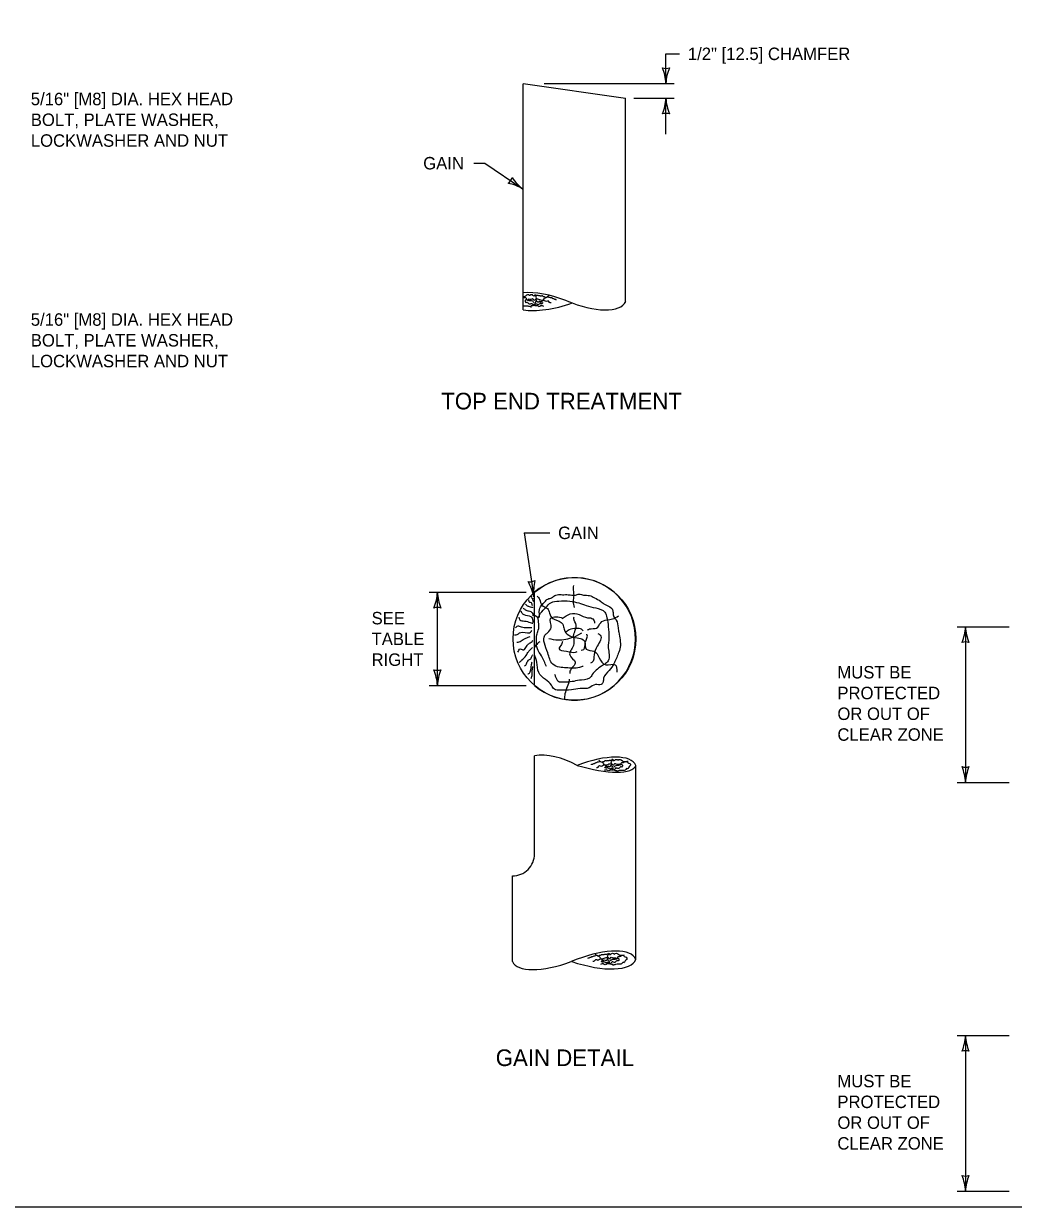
# Model space of a CAD drawing. Extents: x 49991.4 to 50021, y 49987.6 to 50011.4.
# Drawn here: x 50004.08 to 50008.84, y 49987.8 to 49993.5 of the extents above; entities that cross this region are included whole.
import ezdxf

# ---------------------------------------------------------------- set-up
doc = ezdxf.new("R2010")
doc.units = 0
for name, color, linetype in [('Level 1', 7, 'Continuous'), ('Level 2', 7, 'Continuous'), ('Level 3', 7, 'Continuous')]:
    doc.layers.add(name, color=color, linetype=linetype)

msp = doc.modelspace()

# ---------------------------------------------------------------- linework, layer by layer
at = {"layer": 'Level 1'}
for p, q in [((50006.4832, 49992.1206), (50006.4832, 49993.2096)), ((50006.4833, 49993.2102), (50006.9756, 49993.14)), ((50006.9757, 49992.1613), (50006.9757, 49993.14)), ((50006.5375, 49990.3115), (50006.5375, 49990.7608)), ((50006.7246, 49990.5433), (50006.7654, 49990.566)), ((50006.5375, 49989.5007), (50006.5375, 49989.9737)), ((50007.0253, 49988.9933), (50007.0253, 49989.9272)), ((50006.4312, 49988.9827), (50006.4312, 49989.3948)), ((50006.7429, 49988.9933), (50006.7137, 49988.9827))]:
    msp.add_line(p, q, dxfattribs=at)
msp.add_lwpolyline([(49999.3835, 49998.9992), (50016.7501, 49998.9992), (50016.7501, 49987.7988), (49999.3835, 49987.7988)], close=True, dxfattribs=at)
msp.add_circle((50006.7296, 49990.5361), 0.2956, dxfattribs=at)
for centre, radius, start, end in [((50006.7288, 49990.5361), 0.2951, 229.3594, 130.4189), ((50006.4316, 49989.5007), 0.1059, 269.7855, 359.9985)]:
    msp.add_arc(centre, radius, start, end, dxfattribs=at)
for centre, major_axis, ratio, start_param, end_param in [((50006.6565, 49992.069), (-0.2457, 0.0951), 0.387082, 4.71239, 5.63336), ((50006.6874, 49992.2618), (-0.2766, -0.0977), 0.384401, 0.614947, 1.552667), ((50006.7369, 49992.2649), (0.2396, -0.1036), 0.420526, 4.712389, 6.280066), ((50006.7369, 49992.2649), (0.2396, -0.1036), 0.420526, 6.282738, 6.283185), ((50006.6796, 49989.8095), (-0.2192, 0.1177), 0.537084, 4.712389, 5.665612), ((50006.7797, 49989.8321), (0.2457, 0.0951), 0.387082, 0, 1.570796), ((50006.7668, 49990.006), (0.2585, -0.0788), 0.304673, 4.712389, 6.283185), ((50006.7797, 49988.8982), (0.2457, 0.0951), 0.387082, 0, 1.570569), ((50006.6768, 49989.0778), (-0.2457, -0.0951), 0.387082, 0, 1.570796), ((50006.7488, 49989.091), (0.2766, -0.0977), 0.384401, 4.733049, 6.283185)]:
    msp.add_ellipse(centre, major_axis=major_axis, ratio=ratio, start_param=start_param, end_param=end_param, dxfattribs=at)
for points in [[(50006.641, 49992.1677), (50006.641, 49992.1706), (50006.6352, 49992.1706), (50006.6309, 49992.1735), (50006.6266, 49992.1735), (50006.6223, 49992.1778), (50006.6179, 49992.1778), (50006.6121, 49992.1807), (50006.6078, 49992.1807), (50006.5992, 49992.1836), (50006.5906, 49992.1793), (50006.5862, 49992.1836), (50006.5805, 49992.1836), (50006.5761, 49992.1879), (50006.5689, 49992.1865), (50006.5646, 49992.1879), (50006.5603, 49992.1879), (50006.5545, 49992.1893), (50006.5502, 49992.1893), (50006.5444, 49992.1908), (50006.5372, 49992.1908), (50006.5372, 49992.1879), (50006.5329, 49992.1879), (50006.5271, 49992.1922), (50006.5185, 49992.1922), (50006.5141, 49992.1893), (50006.5098, 49992.1922), (50006.4983, 49992.1908), (50006.4882, 49992.1836), (50006.4832, 49992.1836)], [(50006.5343, 49992.1562), (50006.5285, 49992.162), (50006.517, 49992.1648), (50006.504, 49992.1663), (50006.4954, 49992.1778), (50006.4896, 49992.1778), (50006.4853, 49992.1793), (50006.4832, 49992.1801)], [(50006.6179, 49992.1548), (50006.6093, 49992.1562), (50006.6035, 49992.1634), (50006.5948, 49992.1606), (50006.5862, 49992.1648), (50006.5733, 49992.1663), (50006.5631, 49992.1692), (50006.543, 49992.1706), (50006.5343, 49992.1663), (50006.53, 49992.1735), (50006.5243, 49992.1721), (50006.5156, 49992.1706), (50006.507, 49992.1706), (50006.5055, 49992.1663), (50006.4998, 49992.1692), (50006.4954, 49992.1692), (50006.4925, 49992.1606), (50006.4954, 49992.1562), (50006.4998, 49992.1576), (50006.5055, 49992.1548), (50006.5113, 49992.149), (50006.5243, 49992.1519), (50006.5329, 49992.1433), (50006.5444, 49992.1418), (50006.5502, 49992.1418), (50006.5588, 49992.1375), (50006.5675, 49992.1418), (50006.5805, 49992.1389)], [(50006.5488, 49992.162), (50006.5444, 49992.1721), (50006.5473, 49992.1793), (50006.543, 49992.1879), (50006.5401, 49992.1951)], [(50006.5631, 49992.1562), (50006.5805, 49992.1692), (50006.5862, 49992.1764), (50006.6006, 49992.1836), (50006.6064, 49992.1893)], [(50006.4832, 49992.1407), (50006.4839, 49992.1403), (50006.4925, 49992.1403), (50006.5084, 49992.1389), (50006.5228, 49992.1346)], [(50006.5386, 49992.1461), (50006.5285, 49992.1403), (50006.5199, 49992.1403)], [(50006.5747, 49992.1576), (50006.5689, 49992.1591), (50006.5588, 49992.1606), (50006.556, 49992.1576), (50006.5502, 49992.1606), (50006.543, 49992.1606), (50006.5401, 49992.1461), (50006.5458, 49992.1504), (50006.5502, 49992.1476), (50006.5574, 49992.1476), (50006.5646, 49992.1519), (50006.5733, 49992.1504), (50006.5761, 49992.1533), (50006.5776, 49992.1562)], [(50006.5713, 49990.6976), (50006.5866, 49990.7145), (50006.6015, 49990.7282), (50006.6198, 49990.734), (50006.6348, 49990.7448), (50006.6469, 49990.7491), (50006.6724, 49990.7491), (50006.6996, 49990.7491), (50006.7341, 49990.7474), (50006.7525, 49990.7521), (50006.7736, 49990.7474), (50006.8022, 49990.7448), (50006.8264, 49990.734), (50006.855, 49990.7174), (50006.8715, 49990.7053), (50006.908, 49990.6843), (50006.9152, 49990.6679), (50006.917, 49990.6479), (50006.9307, 49990.6268), (50006.9396, 49990.5893), (50006.9426, 49990.568), (50006.95, 49990.4958), (50006.9409, 49990.4655), (50006.9186, 49990.4157), (50006.8972, 49990.3838), (50006.8702, 49990.3476), (50006.8672, 49990.3283), (50006.8581, 49990.3161), (50006.8308, 49990.3161), (50006.8006, 49990.301), (50006.757, 49990.2965), (50006.7147, 49990.2905), (50006.6606, 49990.289), (50006.6334, 49990.2933), (50006.6198, 49990.3129), (50006.5895, 49990.3403), (50006.5577, 49990.3749), (50006.5487, 49990.4233), (50006.5375, 49990.459)], [(50006.7297, 49990.6875), (50006.7246, 49990.7167), (50006.7278, 49990.7451), (50006.7246, 49990.7815), (50006.7262, 49990.7934)], [(50006.4943, 49990.7031), (50006.5061, 49990.6943), (50006.5076, 49990.6943), (50006.5165, 49990.6899), (50006.5268, 49990.6884), (50006.5283, 49990.6854)], [(50006.5091, 49990.7238), (50006.5135, 49990.7135), (50006.5165, 49990.7135), (50006.5238, 49990.7046), (50006.5268, 49990.6987), (50006.5283, 49990.6987)], [(50006.5224, 49990.7415), (50006.5224, 49990.7341), (50006.5297, 49990.7312), (50006.5283, 49990.7267), (50006.5327, 49990.7164)], [(50006.5375, 49990.6508), (50006.5593, 49990.6405), (50006.5608, 49990.6782), (50006.573, 49990.6994)], [(50006.5498, 49990.7423), (50006.5619, 49990.727), (50006.5724, 49990.6985), (50006.5996, 49990.6819), (50006.6103, 49990.6593), (50006.625, 49990.6337), (50006.6313, 49990.6307), (50006.6735, 49990.6067), (50006.6795, 49990.5823), (50006.7021, 49990.5536), (50006.7246, 49990.5433)], [(50006.5529, 49990.6351), (50006.5664, 49990.6593), (50006.5919, 49990.6877), (50006.6162, 49990.7105), (50006.6541, 49990.7181), (50006.7081, 49990.7181), (50006.7503, 49990.7091), (50006.7867, 49990.6968), (50006.832, 49990.685), (50006.8758, 49990.6652), (50006.8862, 49990.638), (50006.8925, 49990.5944), (50006.8954, 49990.5415), (50006.8925, 49990.4933), (50006.8925, 49990.4312), (50006.874, 49990.4132), (50006.8559, 49990.4028), (50006.8349, 49990.3863), (50006.8154, 49990.365), (50006.8108, 49990.3545), (50006.764, 49990.338), (50006.7262, 49990.3317), (50006.6932, 49990.3273), (50006.6722, 49990.3273), (50006.6541, 49990.329), (50006.6404, 49990.3517), (50006.6354, 49990.3653)], [(50006.4619, 49990.6412), (50006.4663, 49990.6279), (50006.4899, 49990.622), (50006.5165, 49990.6146), (50006.5253, 49990.6117), (50006.5297, 49990.6117)], [(50006.4722, 49990.6707), (50006.4752, 49990.6633), (50006.4855, 49990.653), (50006.5194, 49990.6441), (50006.5224, 49990.6412), (50006.5297, 49990.6146)], [(50006.4825, 49990.6854), (50006.4929, 49990.6766), (50006.5091, 49990.6707), (50006.5268, 49990.6618), (50006.5297, 49990.6515), (50006.5297, 49990.6471)], [(50006.5944, 49990.403), (50006.571, 49990.454), (50006.5512, 49990.4886), (50006.5466, 49990.5266), (50006.5482, 49990.5551), (50006.5557, 49990.5779), (50006.5529, 49990.6412)], [(50006.7724, 49990.4057), (50006.7537, 49990.3981), (50006.6901, 49990.3967), (50006.657, 49990.4), (50006.625, 49990.4148), (50006.601, 49990.4693), (50006.5876, 49990.5536), (50006.5996, 49990.5657), (50006.6178, 49990.5914), (50006.6147, 49990.6351), (50006.6416, 49990.6428), (50006.6722, 49990.6365)], [(50006.6706, 49990.6337), (50006.7098, 49990.6565), (50006.7518, 49990.6531), (50006.7927, 49990.638), (50006.8139, 49990.6351), (50006.8259, 49990.6185), (50006.8264, 49990.6111)], [(50006.7246, 49990.5433), (50006.7309, 49990.5703), (50006.7384, 49990.6017), (50006.7262, 49990.6351), (50006.7275, 49990.6421)], [(50006.7918, 49990.5792), (50006.8018, 49990.5839), (50006.8366, 49990.5883), (50006.8559, 49990.6139), (50006.8848, 49990.6275), (50006.9134, 49990.632), (50006.9421, 49990.6472)], [(50006.5238, 49990.5896), (50006.4943, 49990.5896), (50006.4929, 49990.5896), (50006.4693, 49990.594), (50006.4619, 49990.5969), (50006.453, 49990.5955), (50006.4457, 49990.5896)], [(50006.7719, 49990.5749), (50006.764, 49990.5823), (50006.7384, 49990.5867), (50006.7038, 49990.5793), (50006.6888, 49990.5686)], [(50006.4412, 49990.5556), (50006.4486, 49990.5556), (50006.4707, 49990.5674), (50006.5135, 49990.566), (50006.5224, 49990.5733), (50006.5238, 49990.5763)], [(50006.453, 49990.5202), (50006.4589, 49990.5202), (50006.4781, 49990.5306), (50006.4884, 49990.5365), (50006.4958, 49990.5394), (50006.5165, 49990.5483)], [(50006.4575, 49990.4716), (50006.4693, 49990.4878), (50006.4855, 49990.4834), (50006.4988, 49990.4996), (50006.5106, 49990.5129), (50006.5165, 49990.5173), (50006.5253, 49990.5232), (50006.5312, 49990.5291)], [(50006.5622, 49990.5218), (50006.5437, 49990.5053), (50006.5375, 49990.4966)], [(50006.7246, 49990.5433), (50006.6508, 49990.5295), (50006.6058, 49990.5365)], [(50006.6714, 49990.5237), (50006.6674, 49990.5098), (50006.6553, 49990.4886), (50006.6915, 49990.4767), (50006.7354, 49990.4721), (50006.7426, 49990.4748)], [(50006.7246, 49990.5433), (50006.7246, 49990.5038), (50006.7068, 49990.4586), (50006.7336, 49990.4238), (50006.7081, 49990.3801), (50006.7071, 49990.3698)], [(50006.7246, 49990.5433), (50006.779, 49990.5219), (50006.7867, 49990.4873), (50006.8244, 49990.4767), (50006.8486, 49990.445), (50006.8802, 49990.4119), (50006.9253, 49990.4119), (50006.9331, 49990.3757)], [(50006.7624, 49990.4815), (50006.7746, 49990.4858), (50006.782, 49990.5191), (50006.7897, 49990.5581), (50006.789, 49990.559)], [(50006.8416, 49990.5623), (50006.8546, 49990.5536), (50006.8394, 49990.5009), (50006.8244, 49990.46), (50006.8139, 49990.4223), (50006.8071, 49990.4198)], [(50006.4648, 49990.4229), (50006.4752, 49990.4332), (50006.4973, 49990.4568), (50006.5076, 49990.4745), (50006.5194, 49990.4863), (50006.5238, 49990.4907), (50006.5283, 49990.4952)], [(50006.4899, 49990.4052), (50006.4988, 49990.4155), (50006.5076, 49990.4332), (50006.5194, 49990.4406), (50006.5268, 49990.4553), (50006.5297, 49990.4598)], [(50006.5047, 49990.3683), (50006.5061, 49990.3683), (50006.5209, 49990.3963), (50006.5224, 49990.4096), (50006.5253, 49990.4258)], [(50006.5209, 49990.3447), (50006.5253, 49990.3595), (50006.5268, 49990.386), (50006.5297, 49990.4037)], [(50006.7042, 49990.3428), (50006.7038, 49990.338), (50006.6946, 49990.3049), (50006.684, 49990.2715), (50006.6813, 49990.2445)], [(50006.8125, 49989.9304), (50006.8125, 49989.9334), (50006.8183, 49989.9334), (50006.8226, 49989.9362), (50006.8269, 49989.9362), (50006.8312, 49989.9406), (50006.8356, 49989.9406), (50006.8414, 49989.9434), (50006.8457, 49989.9434), (50006.8543, 49989.9463), (50006.863, 49989.942), (50006.8673, 49989.9463), (50006.873, 49989.9463), (50006.8774, 49989.9506), (50006.8846, 49989.9492), (50006.8889, 49989.9506), (50006.8933, 49989.9506), (50006.899, 49989.9521), (50006.9033, 49989.9521), (50006.9091, 49989.9535), (50006.9163, 49989.9535), (50006.9163, 49989.9506), (50006.9206, 49989.9506), (50006.9264, 49989.9549), (50006.935, 49989.9549), (50006.9394, 49989.9521), (50006.9437, 49989.9549), (50006.9552, 49989.9535), (50006.9653, 49989.9463), (50006.9768, 49989.9463), (50006.9826, 49989.9449), (50006.9869, 49989.9406), (50006.9956, 49989.9362), (50006.9999, 49989.929), (50006.9985, 49989.9261), (50006.9913, 49989.9189), (50006.9855, 49989.9103), (50006.9826, 49989.9131), (50006.9768, 49989.9074), (50006.9696, 49989.9031), (50006.961, 49989.9031), (50006.9451, 49989.9016), (50006.9308, 49989.8973)], [(50006.8904, 49989.9189), (50006.873, 49989.9319), (50006.8673, 49989.9391), (50006.8529, 49989.9463), (50006.8471, 49989.9521)], [(50006.9048, 49989.9247), (50006.9091, 49989.9348), (50006.9063, 49989.942), (50006.9105, 49989.9506), (50006.9134, 49989.9579)], [(50006.8356, 49989.9175), (50006.8442, 49989.9189), (50006.85, 49989.9261), (50006.8587, 49989.9233), (50006.8673, 49989.9276), (50006.8802, 49989.929), (50006.8904, 49989.9319), (50006.9105, 49989.9334), (50006.9192, 49989.929), (50006.9235, 49989.9362), (50006.9293, 49989.9348), (50006.9379, 49989.9334), (50006.9466, 49989.9334), (50006.948, 49989.929), (50006.9538, 49989.9319), (50006.9581, 49989.9319), (50006.961, 49989.9233), (50006.9581, 49989.9189), (50006.9538, 49989.9204), (50006.948, 49989.9175), (50006.9423, 49989.9117), (50006.9293, 49989.9146), (50006.9206, 49989.906), (50006.9091, 49989.9045), (50006.9033, 49989.9045), (50006.8947, 49989.9002), (50006.886, 49989.9045), (50006.873, 49989.9016)], [(50006.8788, 49989.9204), (50006.8846, 49989.9218), (50006.8947, 49989.9233), (50006.8975, 49989.9204), (50006.9033, 49989.9233), (50006.9105, 49989.9233), (50006.9134, 49989.9088), (50006.9077, 49989.9131), (50006.9033, 49989.9103), (50006.8961, 49989.9103), (50006.8889, 49989.9146), (50006.8802, 49989.9131), (50006.8774, 49989.9161), (50006.876, 49989.9189)], [(50006.9149, 49989.9088), (50006.925, 49989.9031), (50006.9336, 49989.9031)], [(50006.9192, 49989.9189), (50006.925, 49989.9247), (50006.9365, 49989.9276), (50006.9495, 49989.929), (50006.9581, 49989.9406), (50006.9639, 49989.9406), (50006.9682, 49989.942), (50006.9783, 49989.9463), (50006.9884, 49989.9478)], [(50006.7952, 49988.9969), (50006.7952, 49988.9998), (50006.801, 49988.9998), (50006.8052, 49989.0027), (50006.8096, 49989.0027), (50006.8139, 49989.007), (50006.8182, 49989.007), (50006.824, 49989.0099), (50006.8283, 49989.0099), (50006.837, 49989.0127), (50006.8456, 49989.0084), (50006.85, 49989.0127), (50006.8557, 49989.0127), (50006.86, 49989.0171), (50006.8673, 49989.0157), (50006.8715, 49989.0171), (50006.8759, 49989.0171), (50006.8817, 49989.0185), (50006.886, 49989.0185), (50006.8918, 49989.0199), (50006.899, 49989.0199), (50006.899, 49989.0171), (50006.9033, 49989.0171), (50006.909, 49989.0214), (50006.9177, 49989.0214), (50006.922, 49989.0185), (50006.9263, 49989.0214), (50006.9378, 49989.0199), (50006.948, 49989.0127), (50006.9595, 49989.0127), (50006.9653, 49989.0113), (50006.9696, 49989.007), (50006.9782, 49989.0027), (50006.9826, 49988.9954), (50006.9811, 49988.9926), (50006.9739, 49988.9854), (50006.9681, 49988.9767), (50006.9653, 49988.9796), (50006.9595, 49988.9739), (50006.9523, 49988.9695), (50006.9436, 49988.9695), (50006.9278, 49988.9681), (50006.9134, 49988.9637)], [(50006.8182, 49988.9839), (50006.8269, 49988.9854), (50006.8327, 49988.9926), (50006.8413, 49988.9897), (50006.85, 49988.994), (50006.8629, 49988.9954), (50006.873, 49988.9984), (50006.8932, 49988.9998), (50006.9018, 49988.9954), (50006.9062, 49989.0027), (50006.9119, 49989.0012), (50006.9206, 49988.9998), (50006.9292, 49988.9998), (50006.9307, 49988.9954), (50006.9364, 49988.9984), (50006.9408, 49988.9984), (50006.9436, 49988.9897), (50006.9408, 49988.9854), (50006.9364, 49988.9868), (50006.9307, 49988.9839), (50006.9249, 49988.9782), (50006.9119, 49988.9811), (50006.9033, 49988.9724), (50006.8918, 49988.9709), (50006.886, 49988.9709), (50006.8773, 49988.9666), (50006.8687, 49988.9709), (50006.8557, 49988.9681)], [(50006.873, 49988.9854), (50006.8557, 49988.9984), (50006.85, 49989.0056), (50006.8355, 49989.0127), (50006.8297, 49989.0185)], [(50006.8615, 49988.9868), (50006.8673, 49988.9882), (50006.8773, 49988.9897), (50006.8802, 49988.9868), (50006.886, 49988.9897), (50006.8932, 49988.9897), (50006.896, 49988.9753), (50006.8903, 49988.9796), (50006.886, 49988.9767), (50006.8788, 49988.9767), (50006.8715, 49988.9811), (50006.8629, 49988.9796), (50006.86, 49988.9825), (50006.8586, 49988.9854)], [(50006.8874, 49988.9912), (50006.8918, 49989.0012), (50006.8889, 49989.0084), (50006.8932, 49989.0171), (50006.896, 49989.0243)], [(50006.9018, 49988.9854), (50006.9076, 49988.9912), (50006.9191, 49988.994), (50006.9321, 49988.9954), (50006.9408, 49989.007), (50006.9466, 49989.007), (50006.9508, 49989.0084), (50006.9609, 49989.0127), (50006.9711, 49989.0142)], [(50006.8975, 49988.9753), (50006.9076, 49988.9695), (50006.9163, 49988.9695)]]:
    msp.add_spline(points, degree=3, dxfattribs=at)
at = {"layer": 'Level 3'}
for p, q in [((50007.1701, 49993.3536), (50007.2358, 49993.3536)), ((50007.1701, 49993.2102), (50007.1701, 49993.3536)), ((50006.5833, 49993.2102), (50007.2101, 49993.2102)), ((50007.0157, 49993.14), (50007.2101, 49993.14)), ((50007.1701, 49992.9666), (50007.1701, 49993.14)), ((50006.2444, 49992.8269), (50006.2982, 49992.8269)), ((50006.2982, 49992.8269), (50006.4832, 49992.7014)), ((50006.487, 49991.0468), (50006.6109, 49991.0468)), ((50006.487, 49991.0468), (50006.5343, 49990.7391)), ((50006.0297, 49990.7608), (50006.4975, 49990.7608)), ((50006.0697, 49990.3115), (50006.0697, 49990.7608)), ((50008.5724, 49990.5949), (50008.8227, 49990.5949)), ((50008.6124, 49990.5949), (50008.6124, 49989.8449)), ((50006.0297, 49990.3115), (50006.4975, 49990.3115)), ((50008.5724, 49989.8449), (50008.8227, 49989.8449)), ((50008.5724, 49988.6261), (50008.8227, 49988.6261)), ((50008.6124, 49988.6261), (50008.6124, 49987.8761)), ((50008.5724, 49987.8761), (50008.8227, 49987.8761))]:
    msp.add_line(p, q, dxfattribs=at)
for centre, radius, start, end in [((50007.1701, 49993.3384), 0.0548, 252.1388, 287.8612), ((50006.9374, 49993.1987), 0.233, 2.8273, 22.0772), ((50007.3922, 49993.201), 0.2223, 157.456, 177.6395), ((50006.948, 49993.1492), 0.2223, 337.456, 357.6395), ((50007.4028, 49993.1515), 0.233, 182.8273, 202.0772), ((50007.1701, 49993.0118), 0.0548, 72.1388, 107.8612), ((50006.3771, 49992.7734), 0.0548, 307.9799, 343.7022), ((50006.6155, 49992.88), 0.2223, 213.2971, 233.4806), ((50006.362, 49992.5023), 0.233, 58.6684, 77.9182), ((50006.5148, 49990.8658), 0.0548, 260.878, 296.6003), ((50006.306, 49990.6924), 0.233, 11.5665, 30.8163), ((50006.7552, 49990.7638), 0.2223, 166.1952, 186.3787), ((50005.8476, 49990.77), 0.2223, 337.456, 357.6395), ((50006.3024, 49990.7723), 0.233, 182.8273, 202.0772), ((50006.0697, 49990.6326), 0.0548, 72.1388, 107.8612), ((50008.3903, 49990.6041), 0.2223, 337.456, 357.6395), ((50008.8451, 49990.6064), 0.233, 182.8273, 202.0772), ((50008.6124, 49990.4667), 0.0548, 72.1388, 107.8612), ((50006.0697, 49990.4397), 0.0548, 252.1388, 287.8612), ((50005.837, 49990.3), 0.233, 2.8273, 22.0772), ((50006.2918, 49990.3023), 0.2223, 157.456, 177.6395), ((50008.6124, 49989.9731), 0.0548, 252.1388, 287.8612), ((50008.3797, 49989.8334), 0.233, 2.8273, 22.0772), ((50008.8345, 49989.8358), 0.2223, 157.456, 177.6395), ((50008.3903, 49988.6353), 0.2223, 337.456, 357.6395), ((50008.8451, 49988.6376), 0.233, 182.8273, 202.0772), ((50008.6124, 49988.4979), 0.0548, 72.1388, 107.8612), ((50008.6124, 49988.0043), 0.0548, 252.1388, 287.8612), ((50008.3797, 49987.8646), 0.233, 2.8273, 22.0772), ((50008.8345, 49987.867), 0.2223, 157.456, 177.6395)]:
    msp.add_arc(centre, radius, start, end, dxfattribs=at)

# ---------------------------------------------------------------- texts
at = {"layer": 'Level 2'}
for s, height, p in [('1/2" [12.5] CHAMFER', 0.06, (50007.2758, 49993.3236)), ('5/16" [M8] DIA. HEX HEAD', 0.06, (50004.1121, 49993.1061)), ('BOLT, PLATE WASHER,', 0.06, (50004.1121, 49993.0061)), ('LOCKWASHER AND NUT', 0.06, (50004.1121, 49992.9061)), ('GAIN', 0.06, (50006.0014, 49992.7969)), ('5/16" [M8] DIA. HEX HEAD', 0.06, (50004.1121, 49992.0441)), ('BOLT, PLATE WASHER,', 0.06, (50004.1121, 49991.9441)), ('LOCKWASHER AND NUT', 0.06, (50004.1121, 49991.8441)), ('TOP END TREATMENT', 0.08, (50006.0881, 49991.6412)), ('GAIN', 0.06, (50006.6509, 49991.0168)), ('SEE', 0.06, (50005.7529, 49990.6061)), ('TABLE', 0.06, (50005.7529, 49990.5061)), ('RIGHT', 0.06, (50005.7529, 49990.4061)), ('MUST BE', 0.06, (50007.9956, 49990.3456)), ('PROTECTED', 0.06, (50007.9956, 49990.2456)), ('OR OUT OF', 0.06, (50007.9956, 49990.1456)), ('CLEAR ZONE', 0.06, (50007.9956, 49990.0456)), ('GAIN DETAIL', 0.08, (50006.3506, 49988.4791)), ('MUST BE', 0.06, (50007.9956, 49988.3768)), ('PROTECTED', 0.06, (50007.9956, 49988.2768)), ('OR OUT OF', 0.06, (50007.9956, 49988.1768)), ('CLEAR ZONE', 0.06, (50007.9956, 49988.0768))]:
    msp.add_text(s, height=height, dxfattribs=at).set_placement(p)

doc.saveas('drawing.dxf')
